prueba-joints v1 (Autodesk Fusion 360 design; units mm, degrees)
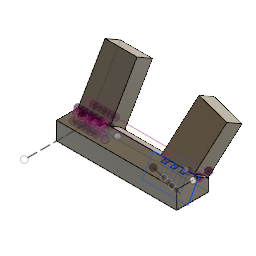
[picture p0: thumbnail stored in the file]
sketch "Sketch1"
  dimension "d1" = 40
  dimension "d2" = 300
  dimension "d3" = 80
extrude "Extrude1" new body sketch "Sketch1" blind 45
sketch "Sketch2" plane through (-40, 0, 0) normal (-1, 0, 0) x axis (0, -1, 0)
  dimension "d6" = 120
  dimension "d7" = 160
  dimension "d8" = 45
extrude "Extrude2" new body sketch "Sketch2" against normal blind 80
copy_paste_bodies "CopyPasteBodies1"
move "Move1"
move "Move2" RotateAngle 12
split "Split1"
remove_body "RemoveBody1"
work_plane "WorkPlane1" RotateAngle -30
sketch "Sketch3" plane through (110, 0, 0) normal (0, 0.5, 0.866) x axis (1, 0, 0)
work_axis "WorkAxis1"
work_plane "WorkPlane4" AlongDistance 26
split "Split3"
remove_body "RemoveBody2"
sketch "Sketch4" plane through (0, 0, 45) normal (0, 0, 1) x axis (-1, 0, 0)
  dimension "d48" = 25
  dimension "d50" = 12.5
  dimension "d51" = 10
  dimension "d52" = 12.5
  dimension "d53" = 10
extrude "Extrude6" cut sketch "Sketch4" to an object
extrude "Extrude4" cut sketch "Sketch4" to an object
sketch "Sketch5" plane through (0, -38.9711, 22.5) normal (0, -0.866, 0.5) x axis (1, 0, 0)
extrude "Extrude5" cut sketch "Sketch5" to an object
work_plane "WorkPlane5" AlongDistance 0
work_plane "WorkPlane6" AlongDistance -15
sketch "Sketch6" plane through (0.4049, -40.1803, 23.1946) normal (0.0087, -0.866, 0.4999) x axis (0.9999, 0.0101, 0)
extrude "Extrude8" cut sketch "Sketch6" to an object
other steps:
base_feature "Base Feature"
